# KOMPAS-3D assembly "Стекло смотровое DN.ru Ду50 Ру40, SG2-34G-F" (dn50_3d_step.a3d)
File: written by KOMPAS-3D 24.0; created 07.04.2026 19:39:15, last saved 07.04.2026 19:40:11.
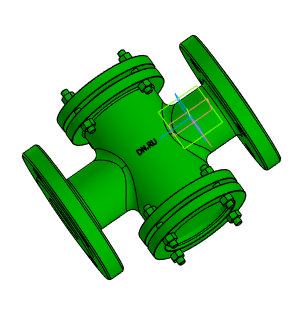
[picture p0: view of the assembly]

Document properties: Автор: Main; Полное имя файла: D:\DN.ru Аутсерс\Стекло смотровое DN.ru\Исходники\Стекло смотровое DN.ru SG2-34G-F тип В ГОСТ 21836-2021 Ду50 Ру40, углеродистая сталь, фланцевое\dn50_3d_step.a3d

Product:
- Component [detail]: Деталь  | qty 1  | pos. 1  | Масса: 10.795401; Автор: Main; source file: ДетальДеталь.m3d
- Component [detail]: Стекло  | qty 2  | pos. 2  | Масса: 0.331901; Автор: Main; source file: СтеклоСтекло.m3d
- Component [detail]: ANSI B18.2.4.2M - M8x1,25 - 13  | designation ANSI B18.2.4.2M - M8x1,25  | qty 1  | pos. 3  | Масса: 0.006562; Автор: Main; source file: ANSI B18.2.4.2M - M8x1,25ANSI B18.2.4.2M - M8x1,25 - 13.m3d
- Component [detail]: ANSI B18.2.4.2M - M8x1,25 - 13  | designation ANSI B18.2.4.2M - M8x1,25  | qty 15  | pos. 3  | Масса: 0.006562; Комментарий: Типы метрических   шестигранных гаек   2; Автор: Main; additional columns: Сталь, мягкая; source file: ANSI B18.2.4.2M - M8x1,25ANSI B18.2.4.2M - M8x1,25 - 13.m3d
- Part/product: Стекло смотровое DN.ru Ду50 Ру40  | designation SG2-34G-F
    Масса: 10.5
    Раздел спецификации: Прочие изделия
    Примечание: D500-00084

Expressions: SG2-34G-F
Referenced files in D:\DN.ru Аутсерс\Стекло смотровое DN.ru\Исходники\Стекло смотровое DN.ru SG2-34G-F тип В ГОСТ 21836-2021 Ду50 Ру40, углеродистая сталь, фланцевое\: ДетальДеталь.m3d, СтеклоСтекло.m3d, ANSI B18.2.4.2M - M8x1,25ANSI B18.2.4.2M - M8x1,25 - 13.m3d
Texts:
  Стекло Стекло (1)
  Стекло Стекло (2)
  ANSI B18.2.4.2M - M8x1,25 ANSI B18.2.4.2M - M8x1,25 - 13 (1)
  ANSI B18.2.4.2M - M8x1,25 ANSI B18.2.4.2M - M8x1,25 - 13 (2)
  ANSI B18.2.4.2M - M8x1,25 ANSI B18.2.4.2M - M8x1,25 - 13 (3)
  ANSI B18.2.4.2M - M8x1,25 ANSI B18.2.4.2M - M8x1,25 - 13 (4)
  ANSI B18.2.4.2M - M8x1,25 ANSI B18.2.4.2M - M8x1,25 - 13 (5)
  ANSI B18.2.4.2M - M8x1,25 ANSI B18.2.4.2M - M8x1,25 - 13 (6)
  ANSI B18.2.4.2M - M8x1,25 ANSI B18.2.4.2M - M8x1,25 - 13 (7)
  ANSI B18.2.4.2M - M8x1,25 ANSI B18.2.4.2M - M8x1,25 - 13 (8)
  ANSI B18.2.4.2M - M8x1,25 ANSI B18.2.4.2M - M8x1,25 - 13 (9)
  ANSI B18.2.4.2M - M8x1,25 ANSI B18.2.4.2M - M8x1,25 - 13 (10)
  ANSI B18.2.4.2M - M8x1,25 ANSI B18.2.4.2M - M8x1,25 - 13 (11)
  ANSI B18.2.4.2M - M8x1,25 ANSI B18.2.4.2M - M8x1,25 - 13 (12)
  ANSI B18.2.4.2M - M8x1,25 ANSI B18.2.4.2M - M8x1,25 - 13 (13)
  ANSI B18.2.4.2M - M8x1,25 ANSI B18.2.4.2M - M8x1,25 - 13 (14)
  ANSI B18.2.4.2M - M8x1,25 ANSI B18.2.4.2M - M8x1,25 - 13 (15)
  ANSI B18.2.4.2M - M8x1,25 ANSI B18.2.4.2M - M8x1,25 - 13 (16)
